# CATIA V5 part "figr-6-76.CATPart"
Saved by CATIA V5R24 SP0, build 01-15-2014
Part number: Part1
Bounding box of the stored display mesh (mm): x 0 to 80, y -59 to 59, z -11 to 11
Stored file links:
  D:\KAVITA\CATIA V5-6R2014 Project_ Kavita\CATIA V5-6R2014_partfiles\Partfiles\c06_catia_v5-6r2014_prt\figr-6-76.CATPart
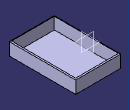
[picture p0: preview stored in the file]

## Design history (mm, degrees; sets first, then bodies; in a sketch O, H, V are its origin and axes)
Body1 (main body)
  Sketch1 on yz-plane, origin (0, 0, 0), H (0, 1, 0), V (0, 0, 1)
    line L1 (59, 11) -> (59, -11)
    line L2 (59, -11) -> (-59, -11)
    line L3 (-59, -11) -> (-59, 11)
    line L4 (-59, 11) -> (59, 11)
    vertical: L1 V, L3 V
    horizontal: L2 H, L4 H
    equidistance: L1 L3 O, L2 L4 O
  Pad1: profile Sketch1, direction (1, 0, 0), length 80
  Shell1: ExtOffset 0, Face face of Pad1 from Sketch1.L4, IntOffset 1, ShellSkin (ExtOffset 0, InitFace end face of Pad1, IntOffset 3; ExtOffset 0, InitFace face of Pad1 from Sketch1.L1, IntOffset 3)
